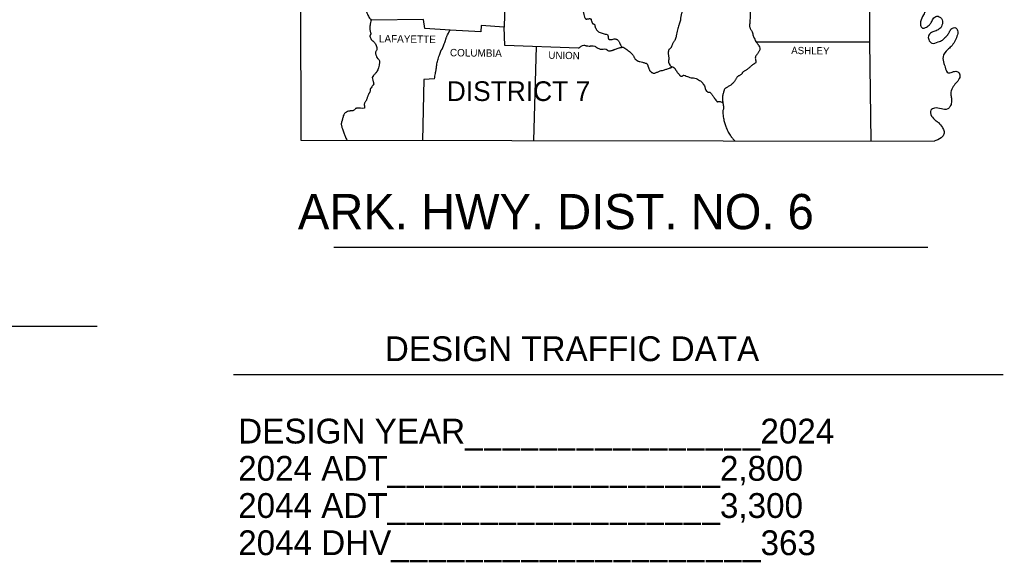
# Model space of a CAD drawing. Extents: x 541267 to 698737, y 790528 to 880942.
# Drawn here: x 633470 to 656765, y 830664 to 843520 of the extents above; entities that cross this region are included whole.
import ezdxf

# ---------------------------------------------------------------- set-up
doc = ezdxf.new("R2010")
doc.units = 0
doc.layers.add('R_Dimension', color=7, linetype='Continuous')
doc.layers.add('R_Draft', color=7, linetype='Continuous')

msp = doc.modelspace()

# ---------------------------------------------------------------- linework, layer by layer
at = {"layer": 'R_Dimension'}
msp.add_line((620144, 836260), (635306, 836260), dxfattribs=at)
at = {"layer": 'R_Draft'}
for p, q in [((640913, 838128), (654978, 838128)), ((638534, 835110), (656765, 835110))]:
    msp.add_line(p, q, dxfattribs=at)
for points in [[(645001, 845406), (644948, 843344), (644396, 843381), (644391, 843229), (643663, 843272)], [(653598, 845439), (653598, 842992), (653631, 840642)], [(640119, 843974), (640128, 840664), (655125, 840639)], [(643033, 843520), (641793, 843508)], [(643663, 843272), (643062, 843307), (643033, 843520)], [(646703, 842845), (644956, 842910), (644948, 843344)], [(645701, 842882), (645636, 840655)], [(650912, 842996), (653598, 842996)], [(643295, 842117), (643041, 842100), (643013, 840659)]]:
    msp.add_lwpolyline(points, dxfattribs=at)
for points in [[(655751, 846278), (655710, 846184), (655665, 846020), (655677, 845881), (655739, 845762), (655837, 845697), (655943, 845603), (655935, 845460), (655874, 845406), (655730, 845443), (655620, 845492), (655526, 845464), (655399, 845402), (655305, 845390), (655309, 845194), (655436, 845054), (655546, 845054), (655673, 845038), (655718, 844891), (655644, 844768), (655522, 844707), (655366, 844780), (655256, 844858), (655145, 844932), (655006, 844969), (654928, 844952), (654891, 844780), (654957, 844625), (655063, 844518), (655162, 844379), (655145, 844277), (655072, 844248), (654941, 844220), (654863, 844179), (654842, 844146), (654883, 844007), (654920, 843856), (654920, 843741), (654875, 843635), (654806, 843471), (654814, 843365), (654863, 843315), (654924, 843332), (655006, 843389), (655059, 843455), (655104, 843536), (655190, 843606), (655297, 843545), (655321, 843418), (655260, 843307), (655174, 843258), (655067, 843217), (654990, 843127), (655010, 843021), (655072, 842964), (655223, 842992), (655325, 843037), (655383, 843094), (655452, 843164), (655489, 843234), (655542, 843307), (655636, 843328), (655681, 843266), (655665, 843127), (655608, 842996), (655530, 842886), (655444, 842808), (655338, 842640), (655358, 842485), (655399, 842358), (655456, 842260), (655554, 842280), (655665, 842292), (655730, 842239), (655722, 842125), (655640, 842014), (655563, 841908), (655522, 841761), (655538, 841658), (655538, 841564), (655505, 841462), (655448, 841405), (655297, 841409), (655137, 841425), (655051, 841376), (655067, 841237), (655162, 841134), (655227, 841081), (655321, 840967), (655362, 840873), (655350, 840791), (655293, 840721), (655125, 840639)], [(647713, 845575), (647710, 845447), (647707, 845384), (647705, 845352), (647702, 845320), (647690, 845257), (647673, 845194), (647662, 845136), (647655, 845107), (647651, 845093), (647648, 845086), (647645, 845079), (647632, 845060), (647617, 845044), (647583, 845014), (647550, 844981), (647518, 844948), (647456, 844874), (647442, 844853), (647430, 844829), (647418, 844806), (647403, 844784), (647350, 844727), (647280, 844670), (647211, 844629), (647133, 844592), (647112, 844585), (647091, 844581), (647069, 844578), (647047, 844572), (647013, 844554), (646999, 844542), (646992, 844535), (646986, 844527), (646975, 844503), (646971, 844477), (646982, 844428), (646998, 844394), (647017, 844359), (647035, 844325), (647051, 844289), (647076, 844224), (647081, 844205), (647085, 844185), (647086, 844165), (647084, 844146), (647055, 844101), (646990, 844064), (646912, 844019), (646843, 843978), (646826, 843965), (646813, 843948), (646802, 843929), (646793, 843909), (646782, 843862), (646785, 843815), (646793, 843787), (646802, 843759), (646810, 843732), (646818, 843704), (646824, 843672), (646830, 843639), (646846, 843581), (646860, 843555), (646871, 843545), (646877, 843540), (646884, 843536), (646894, 843534), (646904, 843536), (646914, 843539), (646924, 843540), (646934, 843541), (646943, 843542), (646961, 843545), (646980, 843544), (646989, 843542), (646994, 843539), (646998, 843536), (647004, 843527), (647006, 843516), (647010, 843495), (647027, 843442), (647039, 843428), (647057, 843420), (647076, 843411), (647088, 843397), (647091, 843387), (647092, 843377), (647094, 843366), (647096, 843356), (647112, 843317), (647133, 843279), (647146, 843262), (647161, 843247), (647194, 843225), (647240, 843209), (647334, 843180), (647383, 843168), (647390, 843165), (647403, 843145), (647409, 843105), (647415, 843068), (647423, 843055), (647436, 843049), (647469, 843050), (647501, 843054), (647550, 843062), (647592, 843060), (647612, 843053), (647622, 843048), (647632, 843041), (647654, 843018), (647669, 842992), (647679, 842972), (647687, 842951), (647696, 842931), (647706, 842910), (647728, 842879), (647739, 842867)], [(649065, 844981), (649068, 844917), (649072, 844854), (649081, 844727), (649088, 844696), (649101, 844666), (649113, 844635), (649116, 844620), (649118, 844604), (649116, 844572), (649112, 844539), (649108, 844506), (649105, 844473), (649101, 844347), (649101, 844232), (649101, 844122), (649101, 844007), (649110, 843925), (649116, 843895), (649123, 843866), (649131, 843836), (649138, 843806), (649148, 843751), (649151, 843723), (649150, 843696), (649146, 843669), (649139, 843643), (649132, 843616), (649126, 843590), (649123, 843565), (649121, 843540), (649118, 843516), (649114, 843491), (649106, 843467), (649098, 843442), (649089, 843418), (649081, 843393), (649052, 843283), (649020, 843139), (649007, 843092), (648999, 843069), (648991, 843045), (648978, 843020), (648963, 842995), (648948, 842972), (648934, 842947), (648924, 842925), (648915, 842902), (648906, 842879), (648897, 842857), (648884, 842842), (648867, 842830), (648851, 842817), (648844, 842809), (648839, 842800), (648830, 842751), (648831, 842702), (648834, 842679), (648838, 842657), (648841, 842634), (648844, 842612), (648843, 842591), (648840, 842571), (648836, 842550), (648835, 842530), (648843, 842490), (648864, 842452), (648878, 842435), (648892, 842420), (648922, 842399)], [(640119, 843974), (640263, 844036), (640324, 844015), (640377, 843962), (640439, 843962), (640471, 844011), (640533, 844015), (640582, 844011), (640635, 844044), (640680, 844064), (640741, 844085), (640786, 844101), (640827, 844146), (640901, 844183), (640987, 844212), (641012, 844252), (641052, 844269), (641134, 844265), (641187, 844289), (641232, 844269), (641273, 844240), (641282, 844134), (641314, 844077), (641363, 843974), (641433, 843921), (641498, 843868), (641523, 843835), (641593, 843774), (641654, 843753), (641683, 843708), (641728, 843602), (641793, 843508)], [(650783, 843790), (650771, 843663), (650767, 843545), (650759, 843430), (650756, 843387), (650757, 843366), (650759, 843344), (650767, 843319), (650781, 843296), (650796, 843274), (650808, 843250), (650836, 843160), (650865, 843082), (650922, 842980), (650935, 842960), (650949, 842941), (650963, 842922), (650975, 842902), (650996, 842847), (650998, 842818), (650992, 842792), (650959, 842734), (650944, 842713), (650928, 842691), (650912, 842670), (650898, 842648), (650891, 842611), (650900, 842568), (650906, 842527), (650894, 842493), (650885, 842486), (650876, 842479), (650857, 842468), (650838, 842457), (650820, 842444), (650774, 842402), (650750, 842381), (650726, 842362), (650673, 842325), (650615, 842288), (650599, 842274), (650584, 842257), (650569, 842239), (650554, 842223), (650532, 842207), (650508, 842193), (650485, 842179), (650464, 842162), (650446, 842137), (650431, 842111), (650416, 842084), (650399, 842059), (650381, 842038), (650364, 842018), (650325, 841981), (650263, 841941), (650242, 841927), (650220, 841915), (650188, 841895), (650178, 841887), (650163, 841871), (650153, 841850), (650141, 841806), (650130, 841768), (650120, 841730), (650113, 841692), (650112, 841654), (650117, 841599), (650124, 841544), (650141, 841445), (650139, 841415), (650130, 841384), (650122, 841353), (650120, 841323), (650141, 841188), (650161, 841081), (650194, 840987), (650239, 840881), (650266, 840831), (650296, 840783), (650348, 840713), (650404, 840647)], [(641793, 843508), (641779, 843455), (641773, 843422), (641769, 843389), (641764, 843295), (641767, 843267), (641774, 843239), (641781, 843212), (641785, 843184), (641782, 843171), (641774, 843158), (641767, 843145), (641764, 843131), (641768, 843112), (641775, 843092), (641797, 843054), (641812, 843036), (641828, 843022), (641844, 843008), (641859, 842992), (641882, 842961), (641904, 842927), (641915, 842903), (641923, 842880), (641929, 842856), (641932, 842833), (641928, 842806), (641914, 842779), (641900, 842753), (641895, 842726), (641901, 842698), (641909, 842671), (641936, 842616), (641945, 842605), (641955, 842595), (641965, 842586), (641973, 842575), (641994, 842509), (641990, 842478), (641983, 842446), (641965, 842382), (641928, 842288), (641920, 842275), (641910, 842263), (641889, 842240), (641867, 842218), (641846, 842194), (641822, 842149), (641834, 842088), (641840, 842063), (641846, 842039), (641852, 842014), (641854, 842002), (641854, 841996), (641854, 841990), (641847, 841975), (641840, 841968), (641834, 841961), (641807, 841926), (641781, 841891), (641773, 841873), (641771, 841853), (641769, 841833), (641764, 841814), (641756, 841797), (641746, 841781), (641736, 841765), (641728, 841748), (641717, 841719), (641707, 841689), (641697, 841659), (641687, 841630), (641675, 841604), (641661, 841580), (641646, 841556), (641634, 841531), (641631, 841500), (641637, 841464), (641640, 841434), (641636, 841424), (641625, 841421), (641543, 841421), (641449, 841421), (641426, 841412), (641406, 841393), (641386, 841373), (641363, 841360), (641344, 841357), (641325, 841357), (641305, 841358), (641286, 841355), (641237, 841342), (641192, 841319), (641172, 841302), (641156, 841284), (641134, 841241), (641114, 841155), (641108, 841134), (641101, 841114), (641089, 841073), (641087, 841038), (641092, 841003), (641102, 840968), (641114, 840934), (641151, 840836), (641179, 840758), (641216, 840662)], [(643295, 842117), (643315, 842247), (643320, 842273), (643325, 842299), (643331, 842324), (643336, 842350), (643339, 842374), (643342, 842399), (643345, 842423), (643348, 842448), (643373, 842558), (643409, 842677), (643442, 842775), (643446, 842785), (643452, 842794), (643465, 842810), (643477, 842827), (643483, 842836), (643487, 842845), (643494, 842865), (643501, 842886), (643508, 842906), (643516, 842927), (643553, 843025), (643561, 843051), (643570, 843077), (643579, 843102), (643589, 843127), (643663, 843272)], [(646703, 842845), (646769, 842890), (646830, 842914), (646861, 842909), (646876, 842905), (646892, 842902), (646957, 842894), (646971, 842895), (646986, 842897), (647000, 842901), (647014, 842902), (647088, 842890), (647105, 842882), (647120, 842872), (647134, 842862), (647149, 842853), (647183, 842834), (647219, 842824), (647289, 842824), (647350, 842824), (647365, 842819), (647377, 842807), (647389, 842795), (647403, 842788), (647427, 842784), (647452, 842783), (647477, 842786), (647501, 842792), (647522, 842800), (647542, 842808), (647563, 842817), (647583, 842824), (647665, 842849), (647693, 842857), (647721, 842864), (647749, 842867), (647763, 842865), (647776, 842861), (647827, 842830), (647874, 842792), (647909, 842764), (647943, 842734), (648001, 842669), (648012, 842651), (648021, 842632), (648030, 842613), (648042, 842595), (648087, 842554), (648104, 842545), (648123, 842537), (648160, 842526), (648217, 842513), (648287, 842493), (648307, 842487), (648316, 842483), (648324, 842477), (648335, 842458), (648343, 842439), (648349, 842418), (648357, 842399), (648362, 842385), (648367, 842372), (648376, 842345), (648389, 842319), (648398, 842305), (648404, 842299), (648410, 842292), (648435, 842272), (648460, 842259), (648486, 842253), (648512, 842256), (648544, 842267), (648575, 842280), (648607, 842293), (648639, 842305), (648741, 842333), (648815, 842358), (648860, 842374), (648870, 842376), (648880, 842376), (648891, 842377), (648901, 842378), (648901, 842379), (648900, 842380), (648895, 842382), (648889, 842385), (648888, 842386), (648889, 842387), (648900, 842392), (648913, 842397), (648938, 842399), (648950, 842394), (648962, 842387), (648983, 842366), (648990, 842355), (648997, 842343), (649004, 842332), (649011, 842321), (649060, 842256), (649082, 842227), (649093, 842213), (649105, 842198), (649115, 842190), (649127, 842184), (649139, 842180), (649150, 842178), (649162, 842181), (649173, 842191), (649184, 842200), (649195, 842202), (649257, 842182), (649310, 842162), (649371, 842145), (649385, 842143), (649398, 842143), (649411, 842142), (649425, 842141), (649494, 842125), (649547, 842096), (649596, 842067), (649646, 842014), (649695, 841932), (649700, 841917), (649703, 841900), (649706, 841883), (649711, 841867), (649735, 841830), (649751, 841815), (649768, 841801), (649781, 841799), (649796, 841803), (649811, 841806), (649822, 841801), (649841, 841775), (649861, 841749), (649899, 841695), (649928, 841654), (649954, 841615), (649970, 841596), (649979, 841588), (649989, 841580), (650000, 841577), (650011, 841578), (650023, 841580), (650034, 841580), (650122, 841564)]]:
    msp.add_spline(points, degree=3, dxfattribs=at)

# ---------------------------------------------------------------- texts
for s, height, rotation, p in [('LAFAYETTE', 175.9, 359.1839, (641977, 842984)), ('COLUMBIA', 175.9, 359.2125, (643659, 842653)), ('ASHLEY', 171.9, 359.2361, (651741, 842706)), ('UNION', 171.9, 358.9584, (645991, 842595))]:
    msp.add_text(s, height=height, rotation=rotation, dxfattribs=at).set_placement(p)
for s, height, p in [('DISTRICT 7', 466.5, (643585, 841593)), ('  ARK. HWY. DIST. NO. 6', 834.74, (639439, 838556)), ('DESIGN TRAFFIC DATA', 587.86, (642118, 835430)), ('DESIGN YEAR________________2024', 587.86, (638645, 833479)), ('2024 ADT__________________2,800', 587.86, (638645, 832597)), ('2044 ADT__________________3,300', 587.86, (638645, 831716)), ('2044 DHV____________________363', 587.86, (638645, 830834))]:
    msp.add_text(s, height=height, dxfattribs=at).set_placement(p)

doc.saveas('drawing.dxf')
